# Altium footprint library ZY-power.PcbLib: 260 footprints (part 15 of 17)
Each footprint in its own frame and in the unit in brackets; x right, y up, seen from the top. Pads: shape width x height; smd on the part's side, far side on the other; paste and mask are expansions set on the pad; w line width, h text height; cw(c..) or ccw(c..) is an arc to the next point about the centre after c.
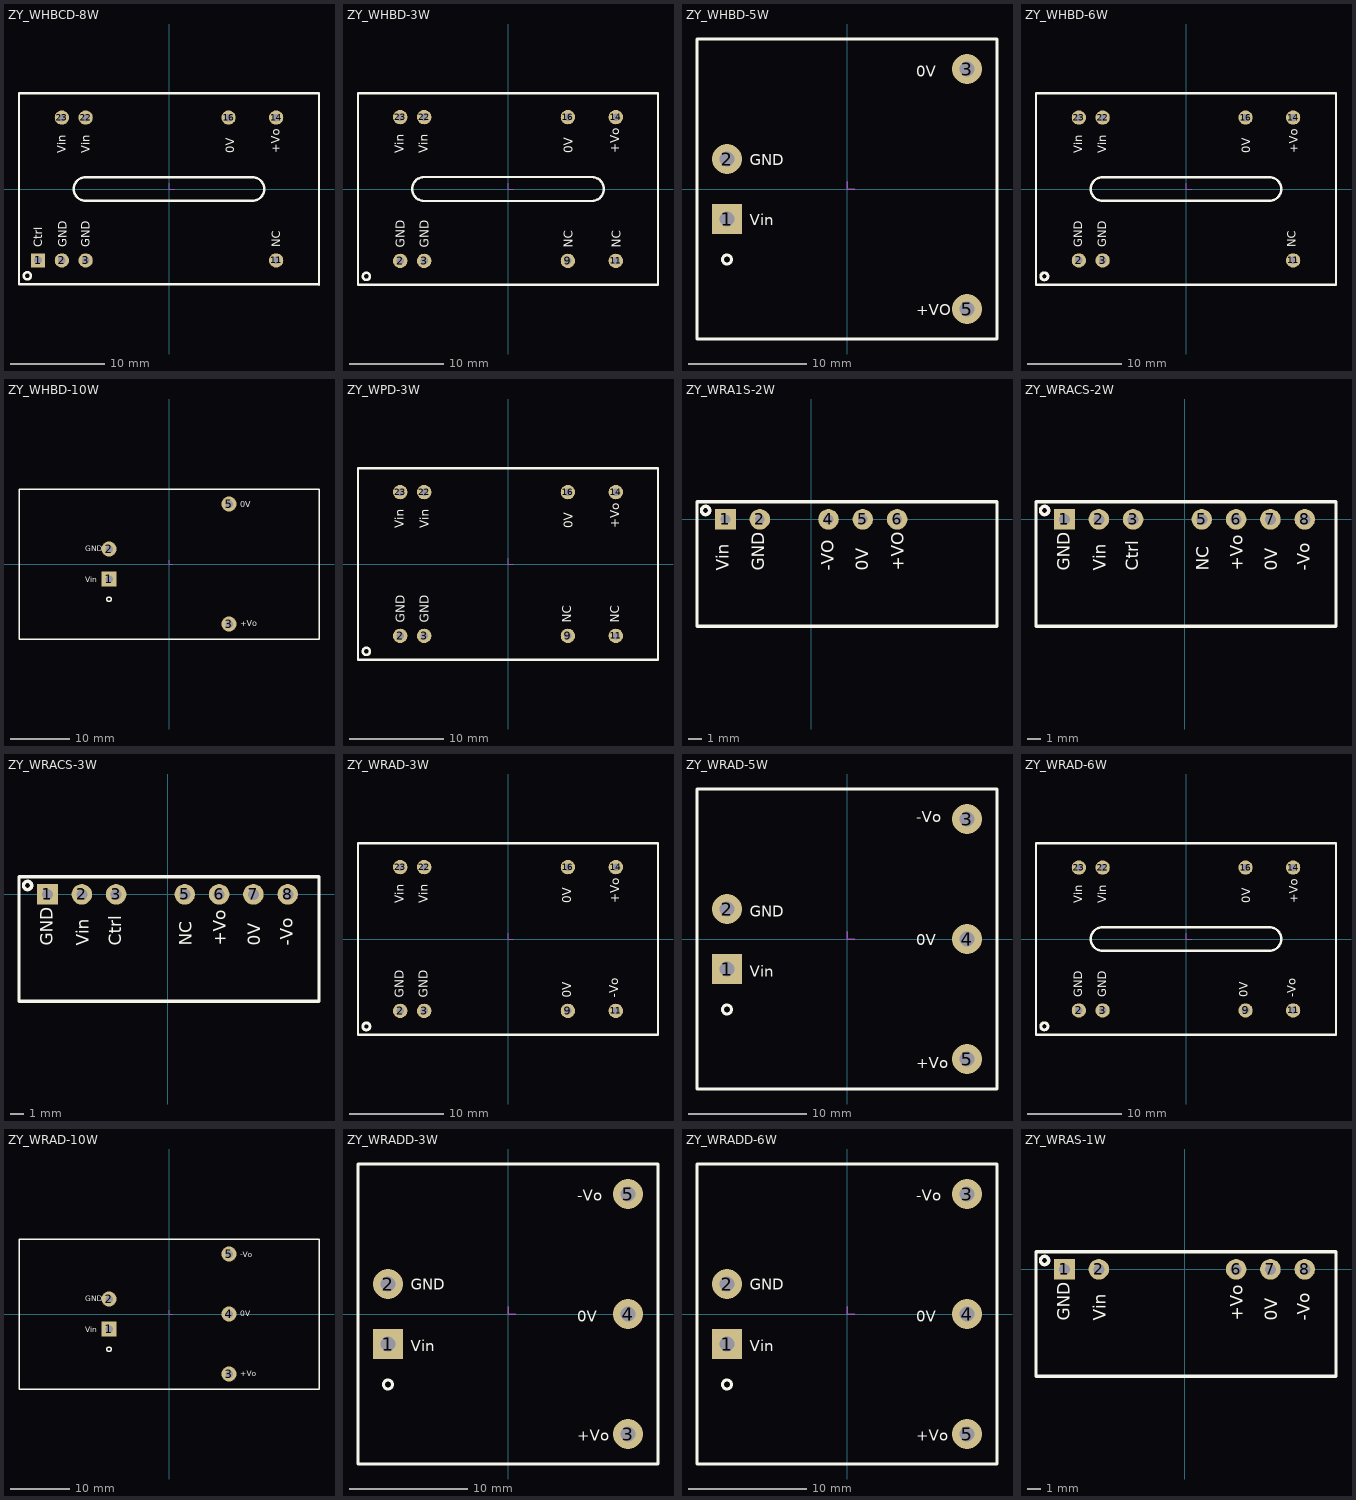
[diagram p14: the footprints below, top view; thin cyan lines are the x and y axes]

## ZY_WHBCD-8W [mil]
height 433.07
pads (8):
  rect 60x60 hole 32: 1(-550,-300)
  round 60 hole 32: 2(-450,-300) 3(-350,-300) 11(450,-300) 14(450,300) 16(250,300) 22(-350,300) 23(-450,300)
Top Overlay:
  circle w10: c-594.92,-364.61 r15
  lines w10: 629.92,-401.57 629.92,401.57 -629.92,401.57 -629.92,-399.61 629.92,-399.61 ; -400,0 cw(c-350,0) -350,50 350,50 cw(c350,0) 400,0 cw(c350,0) 350,-50 -350,-50 cw(c-350,0) -400,0
  text "GND" at -333,-245 h36
  text "Vin" at -433,150 h36
  text "Vin" at -332,150 h36
  text "NC" at 468,-245 h36
  text "Ctrl" at -533,-245 h36
  text "0V" at 275,150 h36
  text "+Vo" at 465,150 h36
  text "GND" at -429,-245 h36
Mechanical 15:
  lines w5: 0,25 0,0 25,0

## ZY_WHBD-3W [mil] "宽压输入隔离稳压单输出电源模块"
height 374.02
pads (8):
  round 60 hole 32: 2(-450,-300) 3(-350,-300) 9(250,-300) 11(450,-300) 14(450,300) 16(250,300) 22(-350,300) 23(-450,300)
Top Overlay:
  circle w10: c-590.98,-364.61 r15
  lines w10: -550,-399.61 -551.38,-399.61 ; -551.38,-399.61 -625.98,-399.61 -625.98,399.61 625.98,399.61 625.98,-399.61 -551.38,-399.61 ; -400,0 cw(c-350,0) -350,50 350,50 cw(c350,0) 400,0 cw(c350,0) 350,-50 -350,-50 cw(c-350,0) -400,0
  text "NC" at 470,-245 h36
  text "NC" at 270,-245 h36
  text "GND" at -430,-245 h36
  text "GND" at -330,-245 h36
  text "Vin" at -435,150 h36
  text "Vin" at -335,150 h36
  text "0V" at 270,150 h36
  text "+Vo" at 465,150 h36
Mechanical 15:
  lines w5: 0,25 0,0 25,0

## ZY_WHBD-5W [mil]
height 460.63
pads (4):
  rect 100x100 hole 50: 1(-400,-100)
  round 100 hole 50: 2(-400,100) 3(400,400) 5(400,-400)
Top Overlay:
  circle w10: c-400,-235 r15
  lines w10: -500,-500 500,-500 500,500 -500,500 -500,-500
  text "0V" at 230,375 h36
  text "+VO" at 230,-420 h36
  text "Vin" at -325,-120 h36
  text "GND" at -325,80 h36
Mechanical 15:
  lines w5: 0,25 0,0 25,0

## ZY_WHBD-6W [mil]
height 413.39
pads (7):
  round 60 hole 32: 2(-450,-300) 3(-350,-300) 11(450,-300) 14(450,300) 16(250,300) 22(-350,300) 23(-450,300)
Top Overlay:
  circle w12: c-594.92,-366.57 r15
  lines w10: -629.92,-401.57 629.92,-401.57 629.92,401.57 -629.92,401.57 -629.92,-401.57 ; -400,0 cw(c-350,0) -350,50 350,50 cw(c350,0) 400,0 cw(c350,0) 350,-50 -350,-50 cw(c-350,0) -400,0
  text "0V" at 270,150 h36
  text "+Vo" at 470,150 h36
  text "NC" at 460,-245 h36
  text "Vin" at -335,150 h36
  text "Vin" at -435,150 h36
  text "GND" at -335,-245 h36
  text "GND" at -435,-245 h36
Mechanical 15:
  lines w5: 0,25 0,0 25,0

## ZY_WHBD-10W [mil]
pads (4):
  rect 100x100 hole 50: 1(-400,-100)
  round 100 hole 50: 2(-400,100) 3(400,-400) 5(400,400)
Top Overlay:
  circle w10: c-400,-235 r15
  lines w10: -1000,-500 -1000,500 1000,500 1000,-500 -1000,-500
  text "+Vo" at 475,-415 h40
  text "0V" at 475,380 h40
  text "GND" at -560,85 h36
  text "Vin" at -560,-120 h36
Mechanical 15:
  lines w5: 0,25 0,0 25,0

## ZY_WPD-3W [mil] "宽压输入非隔离稳压单输出"
height 374.02
pads (8):
  round 60 hole 32: 2(-450,-300) 3(-350,-300) 9(250,-300) 11(450,-300) 14(450,300) 16(250,300) 22(-350,300) 23(-450,300)
Top Overlay:
  circle w10: c-590.98,-364.61 r15
  lines w10: -625.98,-399.61 -625.98,399.61 625.98,399.61 625.98,-399.61 -550,-399.61 -551.38,-399.61 -625.98,-399.61
  text "GND" at -430,-245 h36
  text "GND" at -330,-245 h36
  text "NC" at 265,-245 h36
  text "NC" at 465,-245 h36
  text "+Vo" at 465,150 h36
  text "0V" at 270,150 h36
  text "Vin" at -330,150 h36
  text "Vin" at -435,150 h36
Mechanical 15:
  lines w5: 0,25 0,0 25,0

## ZY_WRA1S-2W [mil]
height 480.31
pads (5):
  rect 60x60 hole 28: 1(-250,0)
  round 60 hole 28: 2(-150,0) 4(50,0) 5(150,0) 6(250,0)
Top Overlay:
  circle w10: c-308,26 r12
  lines w10: 541,-311 -333,-311 -333,51 541,51 541,-310
  text "GND" at -137,-150 h36
  text "Vin" at -241,-150 h36
  text "+VO" at 270,-150 h36
  text "0V" at 166,-150 h36
  text "-VO" at 65,-150 h36

## ZY_WRACS-2W [mil]
pads (7):
  rect 60x60 hole 32: 1(-350,0)
  round 60 hole 32: 2(-250,0) 3(-150,0) 5(50,0) 6(150,0) 7(250,0) 8(350,0)
Top Overlay:
  circle w10: c-408,26 r12
  lines w10: 441,-311 -433,-311 -433,51 441,51 441,-310
  text "GND" at -335,-150 h36
  text "Vin" at -230,-150 h36
  text "Ctrl" at -135,-150 h36
  text "NC" at 70,-150 h36
  text "+Vo" at 170,-150 h36
  text "0V" at 270,-150 h36
  text "-Vo" at 365,-150 h36

## ZY_WRACS-3W [mil]
height 480.31
pads (7):
  rect 60x60 hole 32: 1(-350,0)
  round 60 hole 32: 2(-250,0) 3(-150,0) 5(50,0) 6(150,0) 7(250,0) 8(350,0)
Top Overlay:
  circle w10: c-408,26 r12
  lines w10: 441,-311 -433,-311 -433,51 441,51 441,-310
  text "GND" at -335,-150 h36
  text "Vin" at -230,-150 h36
  text "Ctrl" at -135,-150 h36
  text "NC" at 70,-150 h36
  text "+Vo" at 170,-150 h36
  text "0V" at 270,-150 h36
  text "-Vo" at 365,-150 h36

## ZY_WRAD-3W [mil]
pads (8):
  round 60 hole 32: 2(-450,-300) 3(-350,-300) 9(250,-300) 11(450,-300) 14(450,300) 16(250,300) 22(-350,300) 23(-450,300)
Top Overlay:
  circle w12: c-591,-365 r15
  lines w10: -626,-400 -626,400 626,400 626,-400 -626,-400
  text "Vin" at -435,150 h36
  text "Vin" at -335,150 h36
  text "0V" at 265,150 h36
  text "+Vo" at 465,150 h36
  text "-Vo" at 460,-245 h36
  text "0V" at 265,-245 h36
  text "GND" at -335,-245 h36
  text "GND" at -435,-245 h36
Mechanical 15:
  lines w5: 0,25 0,0 25,0

## ZY_WRAD-5W [mil]
height 460.63
pads (5):
  rect 100x100 hole 50: 1(-400,-100)
  round 100 hole 50: 2(-400,100) 3(400,400) 4(400,0) 5(400,-400)
Top Overlay:
  circle w10: c-400,-235 r15
  lines w10: -500,-500 500,-500 500,500 -500,500 -500,-500
  text "-Vo" at 230,390 h36
  text "+Vo" at 230,-430 h36
  text "Vin" at -325,-125 h36
  text "GND" at -325,75 h36
  text "0V" at 230,-20 h36
Mechanical 15:
  lines w5: 0,25 0,0 25,0

## ZY_WRAD-6W [mil]
height 413.39
pads (8):
  round 60 hole 32: 2(-450,-300) 3(-350,-300) 9(250,-300) 11(450,-300) 14(450,300) 16(250,300) 22(-350,300) 23(-450,300)
Top Overlay:
  circle w12: c-594.92,-366.57 r15
  lines w10: -629.92,-401.57 -629.92,401.57 629.92,401.57 629.92,-401.57 -629.92,-401.57 ; -400,0 ccw(c-350,0) -350,-50 350,-50 ccw(c350,0) 400,0 ccw(c350,0) 350,50 -350,50 ccw(c-350,0) -400,0
  text "0V" at 260,-245 h36
  text "GND" at -435,-245 h36
  text "GND" at -335,-245 h36
  text "Vin" at -435,150 h36
  text "Vin" at -335,150 h36
  text "-Vo" at 460,-245 h36
  text "+Vo" at 470,150 h36
  text "0V" at 270,150 h36
Mechanical 15:
  lines w5: 0,25 0,0 25,0

## ZY_WRAD-10W [mil]
pads (5):
  rect 100x100 hole 50: 1(-400,-100)
  round 100 hole 50: 2(-400,100) 3(400,-400) 4(400,0) 5(400,400)
Top Overlay:
  circle w10: c-400,-235 r15
  lines w10: -1000,-500 1000,-500 1000,500 -1000,500 -1000,-500
  text "Vin" at -560,-120 h36
  text "GND" at -560,85 h36
  text "0V" at 475,-15 h36
  text "+Vo" at 475,-415 h36
  text "-Vo" at 475,380 h36
Mechanical 15:
  lines w5: 0,25 0,0 25,0

## ZY_WRADD-3W [mil]
height 460.63
pads (5):
  rect 100x100 hole 50: 1(-400,-100)
  round 100 hole 50: 2(-400,100) 3(400,-400) 4(400,0) 5(400,400)
Top Overlay:
  circle w10: c-400,-235 r15
  lines w10: -500,-500 500,-500 500,500 -500,500 -500,-500
  text "-Vo" at 230,377 h36
  text "+Vo" at 230,-423 h36
  text "Vin" at -325,-124 h36
  text "GND" at -325,81 h36
  text "0V" at 230,-25 h36
Mechanical 15:
  lines w5: 0,25 0,0 25,0

## ZY_WRADD-6W [mil]
height 460.63
pads (5):
  rect 100x100 hole 50: 1(-400,-100)
  round 100 hole 50: 2(-400,100) 3(400,400) 4(400,0) 5(400,-400)
Top Overlay:
  circle w10: c-400,-235 r15
  lines w10: -500,-500 500,-500 500,500 -500,500 -500,-500
  text "0V" at 230,-25 h36
  text "GND" at -325,81 h36
  text "Vin" at -325,-124 h36
  text "+Vo" at 230,-423 h36
  text "-Vo" at 230,377 h36
Mechanical 15:
  lines w5: 0,25 0,0 25,0

## ZY_WRAS-1W [mil]
height 480.31
pads (5):
  rect 60x60 hole 32: 1(-350,0)
  round 60 hole 32: 2(-250,0) 6(150,0) 7(250,0) 8(350,0)
Top Overlay:
  circle w10: c-408,26 r12
  lines w10: 441,-311 -433,-311 -433,51 441,51 441,-310
  text "GND" at -335,-149 h36
  text "Vin" at -230,-149 h36
  text "+Vo" at 170,-149 h36
  text "0V" at 270,-149 h36
  text "-Vo" at 365,-149 h36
